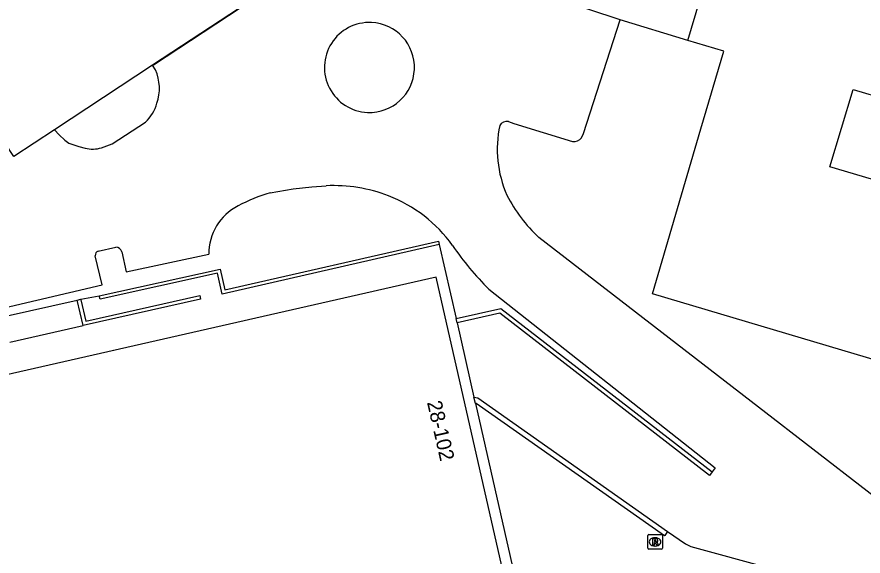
# Model space of a CAD drawing. Extents: x 161141 to 161601, y 381708 to 382245.
# Drawn here: x 161351.2 to 161408.7, y 381823.3 to 381859.9 of the extents above; entities that cross this region are included whole.
import ezdxf

# ---------------------------------------------------------------- set-up
doc = ezdxf.new("R2010")
doc.units = 0
for name, color, linetype in [('IMGEO_Groenvoorziening', 7, 'Continuous'), ('IMGEO_Hek', 7, 'Continuous'), ('IMGEO_Muur', 7, 'Continuous'), ('IMGEO_Pand', 7, 'Continuous'), ('IMGEO_Pand_nummerreeks', 7, 'Continuous'), ('IMGEO_Rijbaan_lokaal_open', 7, 'Continuous'), ('IMGEO_Rioolput', 7, 'Continuous'), ('IMGEO_Voetpad_gesloten', 7, 'Continuous'), ('IMGEO_Voetpad_op_trap', 7, 'Continuous')]:
    doc.layers.add(name, color=color, linetype=linetype)

msp = doc.modelspace()

# ---------------------------------------------------------------- linework, layer by layer
at = {"layer": 'IMGEO_Groenvoorziening'}
for points in [[(161379.908, 381844.444), (161381.05, 381839.415)], [(161355.532, 381840.722), (161356.795, 381840.965)], [(161382.364, 381833.625), (161386.044, 381817.417), (161380.963, 381816.263), (161381.7, 381813.086), (161376.161, 381811.825)]]:
    msp.add_lwpolyline(points, dxfattribs=at)
at = {"layer": 'IMGEO_Hek'}
msp.add_lwpolyline([(161360.471, 381856.669), (161368.964, 381862.254)], dxfattribs=at)
at = {"layer": 'IMGEO_Muur'}
for points in [[(161356.795, 381840.965), (161365.001, 381842.775), (161365.321, 381841.358), (161379.855, 381844.678), (161379.908, 381844.444)], [(161379.908, 381844.444), (161365.139, 381841.071), (161364.82, 381842.488), (161356.848, 381840.731), (161356.795, 381840.965)], [(161355.298, 381840.668), (161355.532, 381840.722)], [(161355.696, 381838.933), (161355.298, 381840.668)], [(161355.532, 381840.722), (161355.539, 381840.688), (161355.876, 381839.221), (161363.619, 381840.967), (161363.671, 381840.733), (161355.696, 381838.933)], [(161381.05, 381839.415), (161384.098, 381840.089), (161398.457, 381828.977)], [(161398.457, 381828.977), (161398.283, 381828.747), (161384.026, 381839.765), (161381.116, 381839.122)], [(161381.116, 381839.122), (161381.05, 381839.415)], [(161382.262, 381834.074), (161382.536, 381834.012), (161395.435, 381824.931)], [(161382.364, 381833.625), (161382.262, 381834.074)], [(161395.435, 381824.931), (161395.242, 381824.651), (161395.226, 381824.628), (161382.405, 381833.633), (161382.364, 381833.625)]]:
    msp.add_lwpolyline(points, dxfattribs=at)
at = {"layer": 'IMGEO_Pand'}
for points in [[(161396.815, 381858.319), (161399.821, 381868.48)], [(161368.964, 381862.254), (161360.411, 381856.63)], [(161413.344, 381847.686), (161410.014, 381836.444), (161394.402, 381841.083), (161397.689, 381852.301), (161399.261, 381857.59), (161396.815, 381858.319)], [(161353.743, 381852.245), (161350.973, 381850.423), (161346.996, 381856.469), (161345.758, 381855.638)], [(161360.411, 381856.63), (161353.743, 381852.245)], [(161413.344, 381847.686), (161406.469, 381849.737), (161408.039, 381854.979), (161414.917, 381852.938)], [(161372.602, 381815.202), (161382.243, 381817.366), (161381.533, 381820.401), (161384.492, 381821.071), (161379.704, 381842.234), (161335.829, 381832.246), (161336.494, 381829.305), (161333.143, 381828.544)]]:
    msp.add_lwpolyline(points, dxfattribs=at)
at = {"layer": 'IMGEO_Rijbaan_lokaal_open'}
for points in [[(161392.214, 381859.719), (161387.882, 381861.165), (161389.294, 381866.012), (161390.047, 381867.09), (161389.223, 381867.644)], [(161389.585, 381851.709), (161389.721, 381851.996), (161392.214, 381859.719)], [(161360.621, 381856.311), (161360.411, 381856.63)], [(161356.943, 381851.025), (161357.679, 381851.295), (161359.926, 381852.758)], [(161384.605, 381852.799), (161384.984, 381852.674), (161388.968, 381851.452)], [(161353.743, 381852.245), (161354.063, 381851.891), (161354.446, 381851.539), (161354.733, 381851.345), (161355.394, 381851.106), (161355.831, 381851.002)], [(161368.405, 381847.968), (161369.966, 381848.223), (161371.243, 381848.361), (161372.222, 381848.435)], [(161412.69, 381824.806), (161401.607, 381833.38), (161386.683, 381844.924)], [(161356.707, 381843.999), (161357.923, 381844.272)], [(161349.286, 381843.739), (161350.04, 381840.078), (161350.317, 381840.141), (161356.981, 381841.703), (161356.517, 381843.681)], [(161358.322, 381843.944), (161358.619, 381842.581), (161364.233, 381843.777)], [(161383.28, 381841.401), (161398.664, 381829.267), (161398.457, 381828.977)], [(161381.116, 381839.122), (161382.262, 381834.074)], [(161395.435, 381824.931), (161396.647, 381824.098), (161397.014, 381823.913), (161407.802, 381820.973)]]:
    msp.add_lwpolyline(points, dxfattribs=at)
for centre, radius, start, end in [((161375.162, 381856.484), 3.059, 87.58326, 267.60119), ((161375.162, 381856.484), 3.059, 267.60197, 87.58247), ((161357.721, 381855.058), 3.159, 341.44108, 23.37512), ((161357.929, 381854.865), 2.904, 313.4615, 343.72954), ((161384.495, 381852.257), 0.553, 78.58059, 149.68807), ((161391.713, 381850.93), 7.861, 168.20877, 203.46151), ((161389.082, 381852.047), 0.606, 259.16034, 326.0662), ((161356.348, 381852.92), 1.986, 254.92393, 287.44588), ((161372.754, 381838.294), 10.155, 68.61842, 93.00158), ((161372.521, 381834.897), 13.704, 107.47696, 117.32043), ((161372.963, 381838.739), 9.665, 35.73286, 68.81125), ((161393.728, 381852.531), 10.368, 207.15062, 227.19873), ((161367.924, 381843.792), 3.691, 117.29862, 180.23837), ((161357.907, 381843.846), 0.426, 13.29849, 87.85734), ((161397.881, 381856.02), 20.662, 214.27938, 225.03631), ((161356.841, 381843.703), 0.325, 114.34721, 183.93748)]:
    msp.add_arc(centre, radius, start, end, dxfattribs=at)
at = {"layer": 'IMGEO_Rioolput'}
for p, q in [((161394.077, 381823.796), (161394.077, 381824.648)), ((161394.152, 381824.722), (161395.004, 381824.722)), ((161394.565, 381824.502), (161394.59, 381824.502)), ((161395.078, 381824.648), (161395.078, 381823.796)), ((161394.588, 381823.942), (161394.563, 381823.942)), ((161395.004, 381823.722), (161394.152, 381823.722))]:
    msp.add_line(p, q, dxfattribs=at)
for points in [[(161394.077, 381823.796), (161394.077, 381824.648)], [(161394.152, 381824.722), (161395.004, 381824.722)], [(161395.078, 381824.648), (161395.078, 381823.796)], [(161394.666, 381824.42), (161394.414, 381824.422), (161394.414, 381824.022)], [(161394.414, 381824.022), (161394.538, 381824.022), (161394.538, 381824.184), (161394.549, 381824.184)], [(161394.592, 381824.341), (161394.538, 381824.341), (161394.538, 381824.26)], [(161394.538, 381824.26), (161394.59, 381824.26)], [(161394.596, 381824.155), (161394.667, 381824.022), (161394.807, 381824.022), (161394.742, 381824.148)], [(161395.004, 381823.722), (161394.152, 381823.722)]]:
    msp.add_lwpolyline(points, dxfattribs=at)
for centre, radius, start, end in [((161394.154, 381824.646), 0.0765, 91.55205, 178.44795), ((161394.154, 381824.646), 0.0765, 91.55205, 178.44795), ((161395.002, 381824.646), 0.0765, 1.55205, 88.44795), ((161395.002, 381824.646), 0.0765, 1.55205, 88.44795), ((161394.548, 381824.131), 0.0533, 26.02933, 88.69889), ((161394.574, 381824.449), 0.19, 274.7715, 282.96867), ((161394.598, 381824.245), 0.0964, 77.00612, 93.18647), ((161394.612, 381824.302), 0.0378, 276.66336, 79.67722), ((161394.665, 381824.31), 0.109, 350.36119, 89.41601), ((161394.663, 381824.31), 0.112, 277.58423, 350.98172), ((161394.647, 381824.095), 0.108, 29.51342, 73.79051), ((161394.154, 381823.798), 0.0765, 181.55205, 268.44795), ((161394.154, 381823.798), 0.0765, 181.55205, 268.44795), ((161395.002, 381823.798), 0.0765, 271.55205, 358.44795), ((161395.002, 381823.798), 0.0765, 271.55205, 358.44795)]:
    msp.add_arc(centre, radius, start, end, dxfattribs=at)
for centre, major_axis, ratio, start_param, end_param in [((161394.564, 381824.222), (-0.387, 0.002), 0.722429, 4.712389, 7.853982), ((161394.589, 381824.222), (-0.39, 0.002), 0.717154, 1.570796, 4.712389)]:
    msp.add_ellipse(centre, major_axis=major_axis, ratio=ratio, start_param=start_param, end_param=end_param, dxfattribs=at)
at = {"layer": 'IMGEO_Voetpad_gesloten'}
msp.add_lwpolyline([(161396.815, 381858.319), (161392.214, 381859.719)], dxfattribs=at)
at = {"layer": 'IMGEO_Voetpad_op_trap'}
for points in [[(161350.325, 381839.554), (161355.298, 381840.668)], [(161350.722, 381837.807), (161355.696, 381838.933)]]:
    msp.add_lwpolyline(points, dxfattribs=at)

# ---------------------------------------------------------------- texts
at = {"layer": 'IMGEO_Pand_nummerreeks'}
msp.add_text('28-102', height=1, rotation=282.7481, dxfattribs=at).set_placement((161379.068, 381833.714))

doc.saveas('drawing.dxf')
